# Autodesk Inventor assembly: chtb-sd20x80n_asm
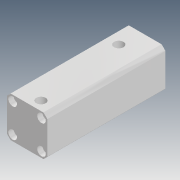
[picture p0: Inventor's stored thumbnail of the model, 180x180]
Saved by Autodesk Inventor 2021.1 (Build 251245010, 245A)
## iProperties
Company: Microsoft
Created: 2018-04
Part Number: chtb-sd20x80n_asm
Description: STEP AP214
Document SubType Name: Assembly
Designer: user
Title: chtb-sd20x80n_asm.STEP
Author: Windows
Revision Number: ÈÎºÎ
Sending System: SolidWorks 2015
Preprocessor: SwSTEP 2.0
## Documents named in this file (4)
- D:\Vault_2016\Projekty\Clamptek\Hydraulic\CHTB\CHTB-20\Inventor\CHTB-SD20x80N\chtb-sd20x80n_asm.iam
- D:\Vault_2016\Projekty\Clamptek\Hydraulic\CHTB\CHTB-20\Inventor\CHTB-SD20x80N\CHTB-SD20X80NBT.ipt
- D:\Vault_2016\Projekty\Clamptek\Hydraulic\CHTB\CHTB-20\Inventor\CHTB-SD20x80N\CHTB-SD20X80NHSG.ipt
- D:\Vault_2016\Projekty\Clamptek\Hydraulic\CHTB\CHTB-20\Inventor\CHTB-SD20x80N\QG.ipt
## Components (3 placed, 3 different names)
1. CHTB-SD20X80NBT_1
2. CHTB-SD20X80NHSG_2
3. QG_3
